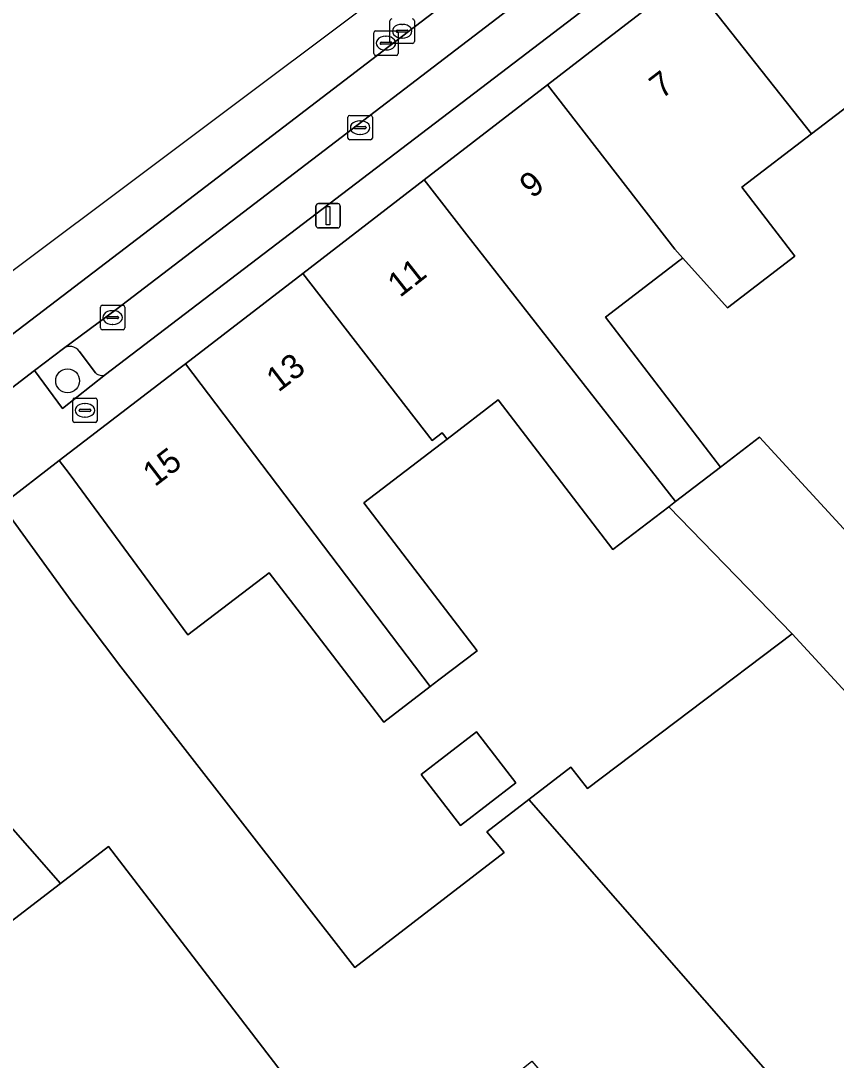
# Model space of a CAD drawing. Extents: x 159499 to 160349, y 382524 to 383273.
# Drawn here: x 159907.71 to 159941.08, y 383200.62 to 383243.18 of the extents above; entities that cross this region are included whole.
import ezdxf

# ---------------------------------------------------------------- set-up
doc = ezdxf.new("R2010")
doc.units = 0
for name, color, linetype in [('IMGEO_Boom', 7, 'Continuous'), ('IMGEO_Brandkraan', 7, 'Continuous'), ('IMGEO_Erf', 7, 'Continuous'), ('IMGEO_Groenvoorziening', 7, 'Continuous'), ('IMGEO_Kolk', 7, 'Continuous'), ('IMGEO_Lichtmast', 7, 'Continuous'), ('IMGEO_Pand', 7, 'Continuous'), ('IMGEO_Pand_nummerreeks', 7, 'Continuous'), ('IMGEO_Parkeervlak_open', 7, 'Continuous'), ('IMGEO_Rijbaan_lokaal_gesloten', 7, 'Continuous'), ('IMGEO_Rijbaan_lokaal_open', 7, 'Continuous'), ('IMGEO_Rioolput', 7, 'Continuous'), ('IMGEO_Voetpad_open', 7, 'Continuous')]:
    doc.layers.add(name, color=color, linetype=linetype)

msp = doc.modelspace()

# ---------------------------------------------------------------- linework, layer by layer
at = {"layer": 'IMGEO_Boom'}
msp.add_circle((159909.63, 383228.437), 0.489, dxfattribs=at)
at = {"layer": 'IMGEO_Brandkraan'}
for p, q in [((159909.839, 383226.801), (159909.839, 383227.653)), ((159909.914, 383227.727), (159910.766, 383227.727)), ((159910.327, 383227.507), (159910.352, 383227.507)), ((159910.84, 383227.653), (159910.84, 383226.801)), ((159910.098, 383227.221), (159910.098, 383227.233)), ((159910.536, 383227.184), (159910.138, 383227.184)), ((159910.141, 383227.27), (159910.539, 383227.27)), ((159910.582, 383227.233), (159910.582, 383227.221)), ((159910.766, 383226.727), (159909.914, 383226.727)), ((159910.35, 383226.947), (159910.325, 383226.947))]:
    msp.add_line(p, q, dxfattribs=at)
for points in [[(159909.839, 383226.801), (159909.839, 383227.653)], [(159909.914, 383227.727), (159910.766, 383227.727)], [(159910.84, 383227.653), (159910.84, 383226.801)], [(159910.766, 383226.727), (159909.914, 383226.727)]]:
    msp.add_lwpolyline(points, dxfattribs=at)
for centre, radius, start, end in [((159909.916, 383227.651), 0.0765, 91.552, 178.448), ((159909.916, 383227.651), 0.0765, 91.552, 178.448), ((159910.764, 383227.651), 0.0765, 1.552, 88.448), ((159910.764, 383227.651), 0.0765, 1.552, 88.448), ((159910.138, 383227.23), 0.0403, 85.8775, 175.7526), ((159910.135, 383227.22), 0.0366, 178.938, 274.7102), ((159910.539, 383227.227), 0.043, 264.8664, 352.4533), ((159910.543, 383227.232), 0.0386, 1.7309, 96.639), ((159909.916, 383226.803), 0.0765, 181.552, 268.448), ((159909.916, 383226.803), 0.0765, 181.552, 268.448), ((159910.764, 383226.803), 0.0765, 271.552, 358.448), ((159910.764, 383226.803), 0.0765, 271.552, 358.448)]:
    msp.add_arc(centre, radius, start, end, dxfattribs=at)
for centre, major_axis, ratio, start_param, end_param in [((159910.326, 383227.227), (-0.387, 0.002), 0.722429, 4.712389, 7.853982), ((159910.351, 383227.227), (-0.39, 0.002), 0.717154, 1.570796, 4.712389)]:
    msp.add_ellipse(centre, major_axis=major_axis, ratio=ratio, start_param=start_param, end_param=end_param, dxfattribs=at)
at = {"layer": 'IMGEO_Erf'}
for points in [[(159946.121, 383243.176), (159940.069, 383238.544), (159937.224, 383236.366), (159939.389, 383233.536), (159936.629, 383231.423), (159934.801, 383233.463), (159934.683, 383233.372), (159931.641, 383231.042), (159936.344, 383224.902), (159937.936, 383226.121), (159945.439, 383217.971)], [(159907.115, 383223.094), (159909.837, 383219.325), (159911.811, 383216.728), (159921.386, 383204.41), (159927.491, 383209.119), (159926.782, 383209.966), (159928.506, 383211.296), (159930.223, 383212.62), (159930.897, 383211.747), (159939.275, 383218.08), (159934.228, 383223.281), (159931.941, 383221.53), (159927.251, 383227.654), (159925.159, 383226.052), (159921.746, 383223.438), (159923.344, 383221.352), (159926.385, 383217.383), (159924.821, 383216.185), (159924.471, 383215.917), (159922.564, 383214.456), (159919.522, 383218.425), (159917.872, 383220.578), (159914.546, 383218.03), (159909.699, 383224.643), (159909.29, 383225.178), (159906.926, 383223.34)]]:
    msp.add_lwpolyline(points, dxfattribs=at)
for points in [[(159927.975, 383211.97), (159925.712, 383210.224), (159924.095, 383212.321), (159926.358, 383214.067)], [(159911.3, 383209.361), (159909.338, 383207.855), (159906.326, 383205.543), (159905.332, 383206.838), (159901.903, 383204.205), (159899.498, 383207.365), (159898.836, 383208.235), (159895.81, 383212.215), (159894.929, 383211.514), (159897.969, 383207.544), (159900.837, 383203.797), (159902.427, 383201.719), (159899.59, 383199.548), (159902.934, 383195.216), (159901.35, 383194.003), (159904.518, 383190.28), (159909.742, 383194.249), (159911.087, 383192.478), (159911.991, 383191.288), (159920.173, 383197.802)]]:
    msp.add_lwpolyline(points, close=True, dxfattribs=at)
at = {"layer": 'IMGEO_Groenvoorziening'}
for points in [[(159909.455, 383229.758), (159908.278, 383228.856), (159909.417, 383227.302), (159911.186, 383228.688)], [(159910.767, 383228.759), (159910.106, 383229.653)]]:
    msp.add_lwpolyline(points, dxfattribs=at)
for centre, radius, start, end in [((159909.727, 383229.375), 0.47, 36.2384, 125.4369), ((159911.032, 383229.049), 0.393, 227.6561, 293.1089)]:
    msp.add_arc(centre, radius, start, end, dxfattribs=at)
at = {"layer": 'IMGEO_Kolk'}
for p, q in [((159921.098, 383238.376), (159921.098, 383239.228)), ((159921.173, 383239.302), (159922.025, 383239.302)), ((159921.586, 383239.082), (159921.611, 383239.082)), ((159922.099, 383239.228), (159922.099, 383238.376)), ((159921.357, 383238.796), (159921.357, 383238.808)), ((159921.795, 383238.759), (159921.397, 383238.759)), ((159921.4, 383238.845), (159921.798, 383238.845)), ((159921.841, 383238.808), (159921.841, 383238.796)), ((159922.025, 383238.302), (159921.173, 383238.302)), ((159921.609, 383238.522), (159921.584, 383238.522)), ((159910.971, 383230.6), (159910.971, 383231.452)), ((159911.046, 383231.526), (159911.898, 383231.526)), ((159911.972, 383231.452), (159911.972, 383230.6)), ((159911.23, 383231.02), (159911.23, 383231.032)), ((159911.668, 383230.983), (159911.27, 383230.983)), ((159911.273, 383231.069), (159911.671, 383231.069)), ((159911.459, 383231.306), (159911.484, 383231.306)), ((159911.714, 383231.032), (159911.714, 383231.02)), ((159911.898, 383230.526), (159911.046, 383230.526)), ((159911.482, 383230.746), (159911.457, 383230.746))]:
    msp.add_line(p, q, dxfattribs=at)
for points in [[(159921.098, 383238.376), (159921.098, 383239.228)], [(159921.173, 383239.302), (159922.025, 383239.302)], [(159922.099, 383239.228), (159922.099, 383238.376)], [(159922.025, 383238.302), (159921.173, 383238.302)], [(159910.971, 383230.6), (159910.971, 383231.452)], [(159911.046, 383231.526), (159911.898, 383231.526)], [(159911.972, 383231.452), (159911.972, 383230.6)], [(159911.898, 383230.526), (159911.046, 383230.526)]]:
    msp.add_lwpolyline(points, dxfattribs=at)
for centre, radius, start, end in [((159921.175, 383239.226), 0.0765, 91.552, 178.448), ((159921.175, 383239.226), 0.0765, 91.552, 178.448), ((159922.023, 383239.226), 0.0765, 1.552, 88.448), ((159922.023, 383239.226), 0.0765, 1.552, 88.448), ((159921.397, 383238.805), 0.0403, 85.8775, 175.7526), ((159921.394, 383238.795), 0.0366, 178.938, 274.7102), ((159921.798, 383238.802), 0.043, 264.8664, 352.4533), ((159921.802, 383238.807), 0.0386, 1.7309, 96.639), ((159921.175, 383238.378), 0.0765, 181.552, 268.448), ((159921.175, 383238.378), 0.0765, 181.552, 268.448), ((159922.023, 383238.378), 0.0765, 271.552, 358.448), ((159922.023, 383238.378), 0.0765, 271.552, 358.448), ((159911.048, 383231.45), 0.0765, 91.552, 178.448), ((159911.048, 383231.45), 0.0765, 91.552, 178.448), ((159911.896, 383231.45), 0.0765, 1.552, 88.448), ((159911.896, 383231.45), 0.0765, 1.552, 88.448), ((159911.27, 383231.029), 0.0403, 85.8775, 175.7526), ((159911.267, 383231.019), 0.0366, 178.938, 274.7102), ((159911.671, 383231.026), 0.043, 264.8664, 352.4533), ((159911.675, 383231.031), 0.0386, 1.7309, 96.639), ((159911.048, 383230.602), 0.0765, 181.552, 268.448), ((159911.048, 383230.602), 0.0765, 181.552, 268.448), ((159911.896, 383230.602), 0.0765, 271.552, 358.448), ((159911.896, 383230.602), 0.0765, 271.552, 358.448)]:
    msp.add_arc(centre, radius, start, end, dxfattribs=at)
for centre, major_axis, ratio, start_param, end_param in [((159921.585, 383238.802), (-0.387, 0.002), 0.722429, 4.712389, 7.853982), ((159921.61, 383238.802), (-0.39, 0.002), 0.717154, 1.570796, 4.712389), ((159911.458, 383231.026), (-0.387, 0.002), 0.722429, 4.712389, 7.853982), ((159911.483, 383231.026), (-0.39, 0.002), 0.717154, 1.570796, 4.712389)]:
    msp.add_ellipse(centre, major_axis=major_axis, ratio=ratio, start_param=start_param, end_param=end_param, dxfattribs=at)
at = {"layer": 'IMGEO_Lichtmast'}
for p, q in [((159919.792, 383234.794), (159919.792, 383235.594)), ((159919.792, 383235.594), (159919.792, 383234.794)), ((159919.892, 383235.694), (159920.682, 383235.694)), ((159920.682, 383235.694), (159919.892, 383235.694)), ((159920.782, 383235.594), (159920.782, 383234.794)), ((159920.782, 383234.794), (159920.782, 383235.594)), ((159920.682, 383234.694), (159919.892, 383234.694)), ((159919.892, 383234.694), (159920.682, 383234.694))]:
    msp.add_line(p, q, dxfattribs=at)
msp.add_lwpolyline([(159920.212, 383235.569), (159920.362, 383235.569), (159920.362, 383234.819), (159920.212, 383234.819), (159920.212, 383235.569)], dxfattribs=at)
for centre, start, end in [((159919.892, 383235.594), 90, 180), ((159919.892, 383235.594), 90, 180), ((159920.682, 383235.594), 0, 90), ((159920.682, 383235.594), 360, 90), ((159919.892, 383234.794), 180, 270), ((159919.892, 383234.794), 180, 270), ((159920.682, 383234.794), 270, 0), ((159920.682, 383234.794), 270, 0)]:
    msp.add_arc(centre, 0.1, start, end, dxfattribs=at)
at = {"layer": 'IMGEO_Pand'}
for points in [[(159943.034, 383247.333), (159941.192, 383249.757), (159934.989, 383244.971), (159940.069, 383238.544), (159946.121, 383243.176)], [(159940.069, 383238.544), (159934.989, 383244.971), (159931.169, 383242.023), (159929.264, 383240.554), (159934.482, 383233.819), (159934.801, 383233.463), (159936.629, 383231.423), (159939.389, 383233.536), (159937.224, 383236.366)], [(159934.683, 383233.372), (159934.801, 383233.463), (159934.482, 383233.819), (159929.264, 383240.554), (159924.217, 383236.662), (159925.965, 383234.418), (159934.508, 383223.496), (159936.344, 383224.902), (159931.641, 383231.042)], [(159925.965, 383234.418), (159924.217, 383236.662), (159919.25, 383232.832), (159924.552, 383225.997), (159924.957, 383226.308), (159925.159, 383226.052), (159927.251, 383227.654), (159931.941, 383221.53), (159934.228, 383223.281), (159934.508, 383223.496)], [(159925.159, 383226.052), (159924.957, 383226.308), (159924.552, 383225.997), (159919.25, 383232.832), (159914.452, 383229.133), (159924.471, 383215.917), (159924.821, 383216.185), (159926.385, 383217.383), (159923.344, 383221.352), (159921.746, 383223.438)], [(159917.872, 383220.578), (159919.522, 383218.425), (159922.564, 383214.456), (159924.471, 383215.917), (159914.452, 383229.133), (159914.185, 383228.927), (159909.29, 383225.178), (159909.699, 383224.643), (159914.546, 383218.03)], [(159937.936, 383226.121), (159936.344, 383224.902), (159934.508, 383223.496), (159934.228, 383223.281), (159939.275, 383218.08), (159942.114, 383214.985), (159945.439, 383217.971)], [(159911.811, 383216.728), (159909.837, 383219.325), (159907.115, 383223.094), (159906.926, 383223.34), (159900.7, 383218.561), (159905.654, 383212.046), (159909.338, 383207.855), (159911.3, 383209.361), (159920.173, 383197.802), (159911.991, 383191.288), (159914.416, 383188.266), (159921.42, 383193.873), (159920.966, 383194.44), (159928.631, 383200.577), (159933.86, 383194.442), (159934.084, 383194.656), (159939.328, 383198.911), (159928.506, 383211.296), (159926.782, 383209.966), (159927.491, 383209.119), (159921.386, 383204.41)], [(159905.654, 383212.046), (159900.7, 383218.561), (159896.852, 383215.608), (159894.565, 383213.853), (159895.81, 383212.215), (159898.836, 383208.235), (159899.498, 383207.365), (159901.903, 383204.205), (159905.332, 383206.838), (159906.326, 383205.543), (159909.338, 383207.855)], [(159942.114, 383214.985), (159939.275, 383218.08), (159930.897, 383211.747), (159930.223, 383212.62), (159928.506, 383211.296), (159939.328, 383198.911), (159934.084, 383194.656), (159934.34, 383194.461), (159939.408, 383188.369), (159954.892, 383200.883), (159950.121, 383206.241)], [(159925.712, 383210.224), (159927.975, 383211.97), (159926.358, 383214.067), (159924.095, 383212.321)]]:
    msp.add_lwpolyline(points, close=True, dxfattribs=at)
at = {"layer": 'IMGEO_Parkeervlak_open'}
for points in [[(159934.028, 383248.514), (159911.61, 383231.36), (159909.455, 383229.758)], [(159911.186, 383228.688), (159934.632, 383246.606)], [(159910.106, 383229.653), (159910.767, 383228.759)]]:
    msp.add_lwpolyline(points, dxfattribs=at)
for centre, radius, start, end in [((159909.727, 383229.375), 0.47, 36.2384, 125.4369), ((159911.032, 383229.049), 0.393, 227.6561, 293.1089)]:
    msp.add_arc(centre, radius, start, end, dxfattribs=at)
at = {"layer": 'IMGEO_Rijbaan_lokaal_gesloten'}
msp.add_lwpolyline([(159883.795, 383210.694), (159887.039, 383213.051), (159892.738, 383217.167), (159893.523, 383217.744), (159899.156, 383221.901), (159902.022, 383224.051), (159903.898, 383225.496), (159908.278, 383228.856), (159909.455, 383229.758), (159911.61, 383231.36), (159934.028, 383248.514), (159934.091, 383248.562), (159934.9, 383249.209), (159940.88, 383253.723), (159948.318, 383259.44), (159949.93, 383260.671), (159949.975, 383260.706), (159951.658, 383262.016), (159950.623, 383263.397), (159934.232, 383250.883), (159922.547, 383241.953), (159913.257, 383234.839), (159906.328, 383229.559)], dxfattribs=at)
at = {"layer": 'IMGEO_Rijbaan_lokaal_open'}
msp.add_lwpolyline([(159906.328, 383229.559), (159913.257, 383234.839), (159922.547, 383241.953), (159934.232, 383250.883), (159950.623, 383263.397), (159949.617, 383264.636), (159870.405, 383205.208), (159782.678, 383149.411)], dxfattribs=at)
at = {"layer": 'IMGEO_Rioolput'}
for p, q in [((159922.818, 383242.325), (159922.818, 383243.177)), ((159923.306, 383243.031), (159923.331, 383243.031)), ((159923.819, 383243.177), (159923.819, 383242.325)), ((159922.154, 383241.835), (159922.154, 383242.687)), ((159922.229, 383242.761), (159923.081, 383242.761)), ((159922.642, 383242.541), (159922.667, 383242.541)), ((159923.077, 383242.745), (159923.077, 383242.757)), ((159923.515, 383242.708), (159923.117, 383242.708)), ((159923.12, 383242.794), (159923.518, 383242.794)), ((159923.155, 383242.687), (159923.155, 383241.835)), ((159923.329, 383242.471), (159923.304, 383242.471)), ((159923.561, 383242.757), (159923.561, 383242.745)), ((159922.413, 383242.255), (159922.413, 383242.267)), ((159922.851, 383242.218), (159922.453, 383242.218)), ((159922.456, 383242.304), (159922.854, 383242.304)), ((159922.665, 383241.981), (159922.64, 383241.981)), ((159923.745, 383242.251), (159922.893, 383242.251)), ((159922.897, 383242.267), (159922.897, 383242.255)), ((159923.081, 383241.761), (159922.229, 383241.761))]:
    msp.add_line(p, q, dxfattribs=at)
for points in [[(159922.818, 383242.325), (159922.818, 383243.177)], [(159923.819, 383243.177), (159923.819, 383242.325)], [(159922.154, 383241.835), (159922.154, 383242.687)], [(159922.229, 383242.761), (159923.081, 383242.761)], [(159923.155, 383242.687), (159923.155, 383241.835)], [(159923.745, 383242.251), (159922.893, 383242.251)], [(159923.081, 383241.761), (159922.229, 383241.761)]]:
    msp.add_lwpolyline(points, dxfattribs=at)
for centre, radius, start, end in [((159922.895, 383243.175), 0.0765, 91.552, 178.448), ((159922.895, 383243.175), 0.0765, 91.552, 178.448), ((159923.743, 383243.175), 0.0765, 1.552, 88.448), ((159923.743, 383243.175), 0.0765, 1.552, 88.448), ((159922.231, 383242.685), 0.0765, 91.552, 178.448), ((159922.231, 383242.685), 0.0765, 91.552, 178.448), ((159923.117, 383242.754), 0.0403, 85.8775, 175.7526), ((159923.114, 383242.744), 0.0366, 178.938, 274.7102), ((159923.079, 383242.685), 0.0765, 1.552, 88.448), ((159923.079, 383242.685), 0.0765, 1.552, 88.448), ((159923.518, 383242.751), 0.043, 264.8664, 352.4533), ((159923.522, 383242.756), 0.0386, 1.7309, 96.639), ((159922.453, 383242.264), 0.0403, 85.8775, 175.7526), ((159922.45, 383242.254), 0.0366, 178.938, 274.7102), ((159922.895, 383242.327), 0.0765, 181.552, 268.448), ((159922.895, 383242.327), 0.0765, 181.552, 268.448), ((159922.854, 383242.261), 0.043, 264.8664, 352.4533), ((159922.858, 383242.266), 0.0386, 1.7309, 96.639), ((159923.743, 383242.327), 0.0765, 271.552, 358.448), ((159923.743, 383242.327), 0.0765, 271.552, 358.448), ((159922.231, 383241.837), 0.0765, 181.552, 268.448), ((159922.231, 383241.837), 0.0765, 181.552, 268.448), ((159923.079, 383241.837), 0.0765, 271.552, 358.448), ((159923.079, 383241.837), 0.0765, 271.552, 358.448)]:
    msp.add_arc(centre, radius, start, end, dxfattribs=at)
for centre, major_axis, ratio, start_param, end_param in [((159923.305, 383242.751), (-0.387, 0.002), 0.722429, 4.712389, 7.853982), ((159923.33, 383242.751), (-0.39, 0.002), 0.717154, 1.570796, 4.712389), ((159922.641, 383242.261), (-0.387, 0.002), 0.722429, 4.712389, 7.853982), ((159922.666, 383242.261), (-0.39, 0.002), 0.717154, 1.570796, 4.712389)]:
    msp.add_ellipse(centre, major_axis=major_axis, ratio=ratio, start_param=start_param, end_param=end_param, dxfattribs=at)
at = {"layer": 'IMGEO_Voetpad_open'}
for points in [[(159950.537, 383258.714), (159942.234, 383252.401), (159936.639, 383248.179), (159934.632, 383246.606), (159911.186, 383228.688), (159909.417, 383227.302), (159908.278, 383228.856), (159903.898, 383225.496)], [(159872.426, 383197.959), (159878.835, 383202.07), (159880.573, 383203.196), (159886.77, 383207.907), (159889.161, 383209.735), (159890.438, 383208.075), (159894.929, 383211.514), (159895.81, 383212.215), (159894.565, 383213.853), (159896.852, 383215.608), (159900.7, 383218.561), (159906.926, 383223.34), (159909.29, 383225.178), (159914.185, 383228.927), (159914.452, 383229.133), (159919.25, 383232.832), (159924.217, 383236.662), (159929.264, 383240.554), (159931.169, 383242.023), (159934.989, 383244.971), (159941.192, 383249.757)]]:
    msp.add_lwpolyline(points, dxfattribs=at)

# ---------------------------------------------------------------- texts
at = {"layer": 'IMGEO_Pand_nummerreeks'}
for s, rotation, p in [('7', 37.4485, (159933.932, 383239.952)), ('9', 39.0356, (159928.64, 383235.87)), ('11', 38.159, (159923.226, 383231.82)), ('13', 37.4485, (159918.252, 383227.943)), ('15', 37.4485, (159913.197, 383224.071))]:
    msp.add_text(s, height=1, rotation=rotation, dxfattribs=at).set_placement(p)

doc.saveas('drawing.dxf')
